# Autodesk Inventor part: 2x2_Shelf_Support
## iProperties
Shininess: 64.0
Length Units: 11272
Angle Units: 11279
Time Units: 11290
Mass Units: 11286
Length Display Precision: 3
Angle Display Precision: 2
Compacted: True
Part Number: 2x2_Shelf_Support
Document SubType Name: Modeling
Created: 2005-01
Designer: John Blackburn
Material: Aluminum-6061
Manufacturer: Standard
Standards Organization: Custom
Density: 0.0
Volumn: 0.0
Area: 0.0
PropertySet Name: Model Information
Control State: 0
Master: False
Checked Out: False
Author: John Blackburn
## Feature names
1. Extrusion1
2. Hole1
